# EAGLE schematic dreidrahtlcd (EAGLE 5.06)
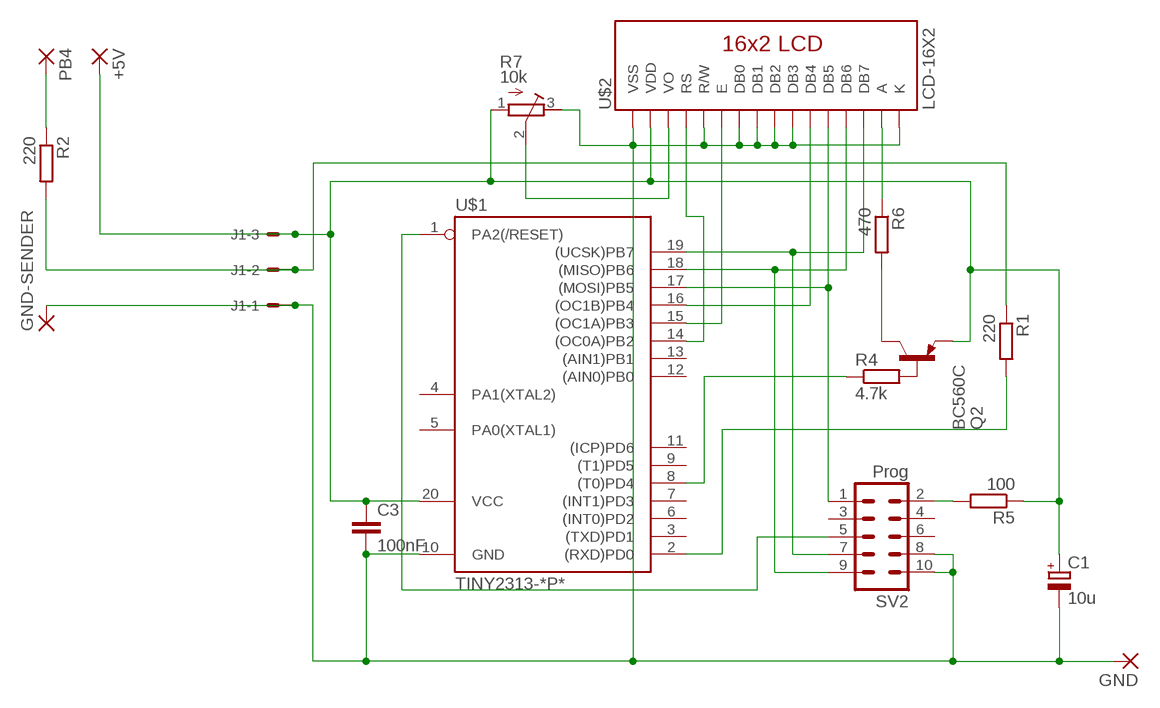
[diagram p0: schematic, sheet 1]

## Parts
+5V  WIREPAD3,81/1,1  [3,81/1,1]
C1  10u  CPOL-EUE3.5-8  [E3,5-8]
C3  100nF  C-EU050-024X044  [C050-024X044]
GND  WIREPAD3,81/1,1  [3,81/1,1]
GND-SENDER  WIREPAD3,81/1,1  [3,81/1,1]
J1  22-27-2031-03  [6410-03]
PB4  WIREPAD3,81/1,1  [3,81/1,1]
Q2  BC560C  [TO92-EBC]
R1  220  R-EU_0204/7  [0204/7]
R2  220  R-EU_0204/7  [0204/7]
R4  4.7k  R-EU_0204/7  [0204/7]
R5  100  R-EU_0204/7  [0204/7]
R6  470  R-EU_0204/7  [0204/7]
R7  10k  R-TRIMM3339P  [RTRIM3339P]
SV2  Prog  ML10  [ML10]
U$1  TINY2313-*P*  [DIL20]
U$2  LCD-16X2  [LCD-16X2]

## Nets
GND: C1.- C3.2 GND-SENDER.1(P) GND.1(P) J1.1 R7.3(A) SV2.8 SV2.10 U$1.10(GND) U$2.1(VSS) U$2.5(R/W) U$2.7(DB0) U$2.8(DB1) U$2.9(DB2) U$2.10(DB3) U$2.16(K)
N$1: SV2.1 U$1.17((MOSI)PB5) U$2.12(DB5)
N$3: SV2.9 U$1.18((MISO)PB6) U$2.13(DB6)
N$5: R1.2 U$1.2((RXD)PD0)
N$6: J1.2 R1.1 R2.2
N$7: PB4.1(P) R2.1
N$8: Q2.C R6.2
N$9: U$1.14((OC0A)PB2) U$2.4(RS)
N$10: R5.2 SV2.2
N$11: SV2.7 U$1.19((UCSK)PB7) U$2.14(DB7)
N$12: R4.1 U$1.8((T0)PD4)
N$13: Q2.B R4.2
N$14: U$1.15((OC1A)PB3) U$2.6(E)
N$15: SV2.5 U$1.1(PA2(/RESET))
N$16: R6.1 U$2.15(A)
N$17: U$1.16((OC1B)PB4) U$2.11(DB4)
N$19: R7.2(S) U$2.3(VO)
VCC: +5V.1(P) C1.+ C3.1 J1.3 Q2.E R5.1 R7.1(E) U$1.20(VCC) U$2.2(VDD)
Unconnected: SV2.3 SV2.4 SV2.6 U$1.3((TXD)PD1) U$1.4(PA1(XTAL2)) U$1.5(PA0(XTAL1)) U$1.6((INT0)PD2) U$1.7((INT1)PD3) U$1.9((T1)PD5) U$1.11((ICP)PD6) U$1.12((AIN0)PB0) U$1.13((AIN1)PB1)

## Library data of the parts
+5V GND GND-SENDER PB4 = wirepad:WIREPAD: Wire PAD connect wire on PCB
C1 = rcl:CPOL-EU: POLARIZED CAPACITOR, European symbol
C3 = rcl:C-EU: CAPACITOR, European symbol
J1 = con-molex:22-?-03: CONNECTOR wire to board 2.54 mm (.1 inch) pitch header
Q2 = transistor-pnp:BC560*: PNP Transistror
R1 R2 R4-R6 = rcl:R-EU_: RESISTOR, European symbol
R7 = resistor:R-TRIMM: Trimm resistor
SV2 = con-harting-ml:ML10: HARTING
U$1 = avr-6:TINY2313*: Atmel Tiny2313 2K Flash, 128 bytes EEPROM, 128 bytes RAM
U$2 = SparkFun:LCD-16X2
